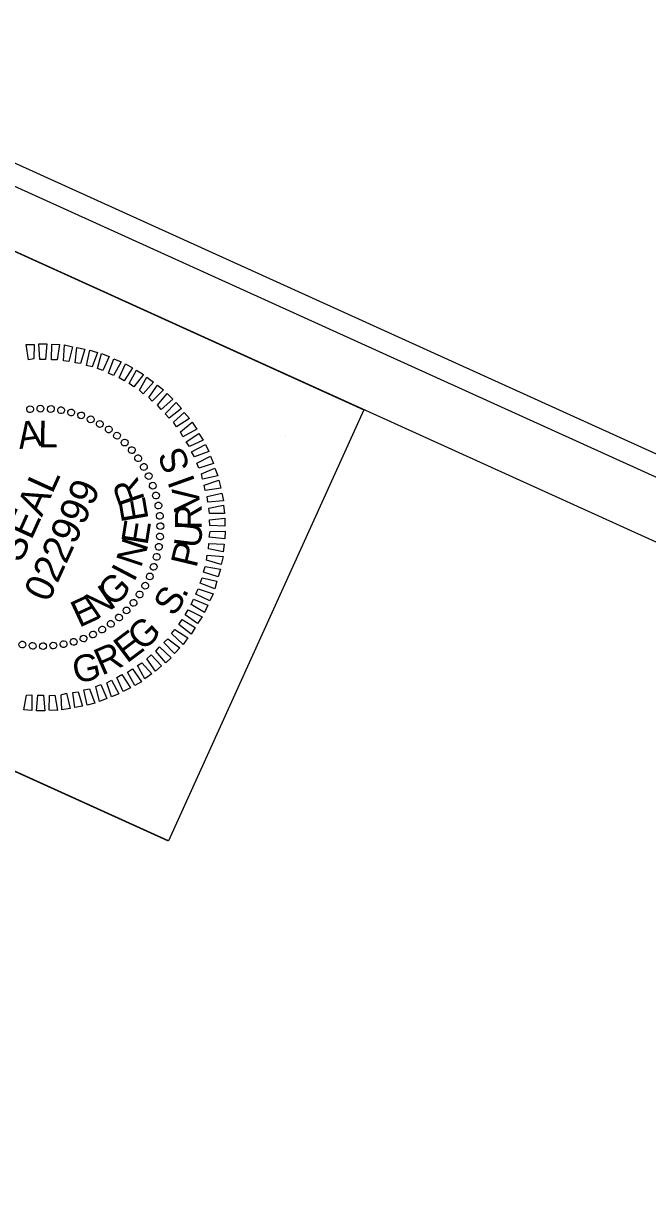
# Model space of a CAD drawing. Extents: x 1744741 to 2014229, y 466994 to 951338.
# Drawn here: x 2011187 to 2011483, y 477413 to 477976 of the extents above; entities that cross this region are included whole.
import ezdxf

# ---------------------------------------------------------------- set-up
doc = ezdxf.new("R2010")
doc.units = 0
for name, color, linetype in [('Prop Guardrail', 7, 'Continuous'), ('Sheet Plan CELL', 7, 'Continuous'), ('Sheet Plot Border Inside CELL', 7, 'Continuous'), ('Sheet Plot Border Outside CELL', 7, 'Continuous')]:
    doc.layers.add(name, color=color, linetype=linetype)

msp = doc.modelspace()

# ---------------------------------------------------------------- linework, layer by layer
at = {"layer": 'Prop Guardrail'}
for p, q in [((2011189.81, 477792.44), (2011189.81, 477792.44)), ((2011194.63, 477792.73), (2011194.63, 477792.73)), ((2011199.52, 477792.61), (2011199.52, 477792.61)), ((2011204.43, 477791.99), (2011204.43, 477791.99)), ((2011209.36, 477790.87), (2011209.36, 477790.87)), ((2011213.94, 477789.53), (2011213.94, 477789.53)), ((2011218.54, 477787.7), (2011218.54, 477787.7)), ((2011222.96, 477785.45), (2011222.96, 477785.45)), ((2011227.19, 477782.79), (2011227.19, 477782.79)), ((2011231.07, 477779.92), (2011231.07, 477779.92)), ((2011311.39, 477779.45), (2011311.39, 477779.45)), ((2011234.77, 477776.63), (2011234.77, 477776.63)), ((2011238.08, 477773.03), (2011238.08, 477773.03)), ((2011241.25, 477769.13), (2011241.25, 477769.13)), ((2011243.82, 477765), (2011243.82, 477765)), ((2011246.31, 477760.66), (2011246.31, 477760.66)), ((2011248.19, 477756.1), (2011248.19, 477756.1)), ((2011249.78, 477751.43), (2011249.78, 477751.43)), ((2011250.82, 477746.63), (2011250.82, 477746.63)), ((2011251.56, 477741.73), (2011251.56, 477741.73)), ((2011195.23, 477736.26), (2011195.23, 477736.26)), ((2011251.8, 477736.8), (2011251.8, 477736.8)), ((2011251.06, 477727.01), (2011251.06, 477727.01)), ((2011251.58, 477731.96), (2011251.58, 477731.96)), ((2011249.88, 477722.23), (2011249.88, 477722.23)), ((2011248.5, 477717.55), (2011248.5, 477717.55)), ((2011246.66, 477712.94), (2011246.66, 477712.94)), ((2011241.8, 477704.4), (2011241.8, 477704.4)), ((2011244.42, 477708.53), (2011244.42, 477708.53)), ((2011238.99, 477700.37), (2011238.99, 477700.37)), ((2011232.1, 477693.36), (2011232.1, 477693.36)), ((2011235.6, 477696.71), (2011235.6, 477696.71)), ((2011224.07, 477687.61), (2011224.07, 477687.61)), ((2011228.24, 477690.29), (2011228.24, 477690.29)), ((2011210.54, 477681.76), (2011210.54, 477681.76)), ((2011215.22, 477683.35), (2011215.22, 477683.35)), ((2011219.78, 477685.23), (2011219.78, 477685.23)), ((2011190.93, 477679.91), (2011190.93, 477679.91)), ((2011195.82, 477679.79), (2011195.82, 477679.79)), ((2011200.84, 477679.98), (2011200.84, 477679.98)), ((2011205.65, 477680.77), (2011205.65, 477680.77))]:
    msp.add_line(p, q, dxfattribs=at)
for points in [[(2011189.07, 477815.88), (2011187.94, 477823.18), (2011191.66, 477823.22), (2011191.47, 477816.27)], [(2011194.35, 477816.08), (2011193.97, 477823.41), (2011197.69, 477823.45), (2011197.07, 477816.08)], [(2011199.95, 477815.89), (2011200.07, 477823.24), (2011203.7, 477823.08), (2011202.66, 477815.89)], [(2011205.65, 477815.4), (2011206.12, 477822.97), (2011209.93, 477822.11), (2011208.23, 477815.1)], [(2011211.13, 477814.4), (2011212.01, 477821.78), (2011215.81, 477820.92), (2011213.71, 477814.1)], [(2011216.51, 477813.2), (2011218.1, 477820.51), (2011221.77, 477819.34), (2011219.2, 477812.59)], [(2011221.76, 477811.68), (2011223.75, 477818.81), (2011227.33, 477817.43), (2011224.31, 477810.77)], [(2011226.97, 477809.57), (2011229.58, 477816.41), (2011233.06, 477814.83), (2011229.43, 477808.45)], [(2011232.09, 477807.24), (2011235.11, 477813.9), (2011238.5, 477812.12), (2011234.46, 477805.92)], [(2011236.83, 477804.61), (2011240.41, 477810.88), (2011243.71, 477808.9), (2011239.05, 477802.98)], [(2011241.78, 477801.37), (2011245.32, 477807.55), (2011248.48, 477805.25), (2011243.51, 477799.72)], [(2011246.14, 477797.91), (2011250.3, 477803.81), (2011253.25, 477801.61), (2011247.87, 477796.27)], [(2011250.41, 477794.25), (2011254.93, 477799.86), (2011257.65, 477797.14), (2011252, 477792.29)], [(2011254.04, 477790.26), (2011259.17, 477795.59), (2011261.8, 477792.67), (2011255.83, 477788.21)], [(2011257.87, 477786.17), (2011262.98, 477790.9), (2011265.61, 477787.98), (2011259.36, 477784.02)], [(2011261.26, 477781.67), (2011266.78, 477786.21), (2011268.97, 477782.87), (2011262.41, 477779.3)], [(2011264.02, 477776.84), (2011270.05, 477780.9), (2011272.04, 477777.65), (2011265.51, 477774.68)], [(2011266.56, 477772.11), (2011273.12, 477775.68), (2011274.76, 477772.22), (2011267.96, 477769.74)], [(2011269.08, 477766.76), (2011275.55, 477770.13), (2011276.89, 477766.56), (2011269.98, 477764.38)], [(2011271.24, 477761.71), (2011277.63, 477764.37), (2011278.98, 477760.8), (2011271.79, 477759.11)], [(2011272.5, 477756.32), (2011279.46, 477758.6), (2011280.46, 477754.81), (2011273.05, 477753.72)], [(2011274.01, 477750.94), (2011280.9, 477752.51), (2011281.74, 477748.92), (2011274.22, 477748.13)], [(2011274.68, 477745.33), (2011281.77, 477746.81), (2011282.18, 477742.79), (2011275.03, 477742.82)], [(2011275.14, 477739.81), (2011282.41, 477740.59), (2011282.41, 477736.76), (2011275.15, 477737.09)], [(2011275.35, 477734.28), (2011282.55, 477734.35), (2011282.43, 477730.82), (2011274.85, 477731.54)], [(2011274.76, 477728.62), (2011282.03, 477728.29), (2011281.61, 477724.65), (2011274.61, 477726.09)], [(2011273.97, 477723.05), (2011281.55, 477722.33), (2011280.59, 477718.57), (2011273.61, 477720.62)], [(2011272.97, 477717.57), (2011280.32, 477716.34), (2011279.19, 477712.77), (2011272.27, 477714.93)], [(2011271.56, 477712.28), (2011278.47, 477710.63), (2011277.55, 477706.97), (2011270.65, 477709.73)], [(2011269.65, 477706.97), (2011276.74, 477704.62), (2011275.2, 477701.24), (2011268.53, 477704.51)], [(2011267.42, 477702.05), (2011274.27, 477699.19), (2011272.74, 477695.81), (2011266.3, 477699.59)], [(2011264.89, 477697.02), (2011271.52, 477693.65), (2011269.37, 477690.55), (2011263.57, 477694.66)], [(2011258.65, 477687.62), (2011264.79, 477683.73), (2011262.6, 477680.52), (2011257.06, 477685.75)], [(2011262.05, 477692.38), (2011268.23, 477688.59), (2011266.29, 477685.4), (2011260.52, 477690.11)], [(2011255.2, 477683.26), (2011260.9, 477678.95), (2011258.43, 477676.24), (2011253.4, 477681.48)], [(2011251.26, 477679.49), (2011256.8, 477674.26), (2011254.22, 477671.85), (2011249.53, 477677.31)], [(2011242.89, 477671.92), (2011247.63, 477666.56), (2011244.34, 477664.22), (2011240.78, 477670.53)], [(2011247.28, 477675.61), (2011252.31, 477670.36), (2011249.44, 477667.84), (2011245.23, 477673.82)], [(2011233.39, 477666.22), (2011237.46, 477659.93), (2011233.95, 477658.18), (2011231.07, 477664.92)], [(2011238.37, 477669.03), (2011242.73, 477662.85), (2011239.48, 477661.11), (2011236.12, 477667.33)], [(2011217.99, 477659.49), (2011220.61, 477652.74), (2011216.93, 477651.69), (2011215.29, 477658.98)], [(2011223.35, 477661.51), (2011226.27, 477654.87), (2011222.7, 477653.53), (2011220.97, 477660.61)], [(2011228.5, 477663.62), (2011231.98, 477657.1), (2011228.4, 477655.76), (2011226.19, 477662.32)], [(2011190.51, 477656.63), (2011190.59, 477649.18), (2011186.75, 477649.44), (2011187.99, 477656.53)], [(2011196.1, 477656.44), (2011196.69, 477649.01), (2011192.76, 477649.06), (2011193.38, 477656.44)], [(2011201.59, 477656.55), (2011202.72, 477649.24), (2011198.79, 477649.29), (2011198.98, 477656.25)], [(2011207.14, 477657.36), (2011208.78, 477650.08), (2011204.82, 477649.52), (2011204.6, 477656.66)], [(2011212.65, 477658.08), (2011214.73, 477651.21), (2011210.98, 477650.56), (2011210.05, 477657.78)]]:
    msp.add_lwpolyline(points, close=True, dxfattribs=at)
for centre, major_axis in [((2011189.75, 477792.36), (-0.16, 1.61)), ((2011194.67, 477792.63), (-0.02, 1.62)), ((2011199.59, 477792.47), (0.12, 1.62)), ((2011204.47, 477791.88), (0.26, 1.6)), ((2011209.29, 477790.86), (0.4, 1.57)), ((2011214, 477789.43), (0.54, 1.53)), ((2011218.57, 477787.6), (0.67, 1.48)), ((2011222.96, 477785.37), (0.79, 1.41)), ((2011227.14, 477782.77), (0.91, 1.34)), ((2011231.08, 477779.82), (1.03, 1.25)), ((2011234.74, 477776.53), (1.13, 1.16)), ((2011238.11, 477772.94), (1.23, 1.05)), ((2011241.15, 477769.06), (1.32, 0.94)), ((2011243.84, 477764.94), (1.39, 0.83)), ((2011246.16, 477760.6), (1.46, 0.7)), ((2011248.09, 477756.07), (1.52, 0.57)), ((2011249.62, 477751.39), (1.56, 0.44)), ((2011250.74, 477746.6), (1.59, 0.3)), ((2011251.43, 477741.72), (1.61, 0.16)), ((2011251.7, 477736.81), (1.62, 0.02)), ((2011251.54, 477731.89), (1.62, -0.12)), ((2011250.95, 477727), (1.6, -0.26)), ((2011249.94, 477722.18), (1.57, -0.4)), ((2011248.51, 477717.47), (1.53, -0.54)), ((2011244.45, 477708.51), (1.41, -0.79)), ((2011246.67, 477712.91), (1.48, -0.67)), ((2011241.84, 477704.33), (1.34, -0.91)), ((2011235.6, 477696.73), (1.16, -1.13)), ((2011238.89, 477700.4), (1.25, -1.03)), ((2011232.01, 477693.37), (1.05, -1.23)), ((2011219.67, 477685.32), (0.7, -1.46)), ((2011224.01, 477687.64), (0.83, -1.39)), ((2011228.14, 477690.33), (0.94, -1.32)), ((2011186.07, 477680.53), (-0.26, -1.6)), ((2011190.96, 477679.94), (-0.12, -1.62)), ((2011195.88, 477679.77), (0.02, -1.62)), ((2011200.8, 477680.04), (0.16, -1.61)), ((2011205.67, 477680.74), (0.3, -1.59)), ((2011210.47, 477681.85), (0.44, -1.56)), ((2011215.14, 477683.39), (0.57, -1.52))]:
    msp.add_ellipse(centre, major_axis=major_axis, ratio=0.999708, dxfattribs=at)
at = {"layer": 'Sheet Plan CELL'}
msp.add_line((2011024.95, 477691.7), (2011255.4, 477587.24), dxfattribs=at)
for points in [[(2011066.5, 477919.9), (2009673.19, 474845.92), (2011824.97, 473870.61), (2013218.28, 476944.58)], [(2011024.95, 477691.7), (2011117.84, 477896.63), (2011348.39, 477792.13), (2011255.5, 477587.2)]]:
    msp.add_lwpolyline(points, close=True, dxfattribs=at)
at = {"layer": 'Sheet Plot Border Inside CELL'}
msp.add_lwpolyline([(2011687.52, 473553.71), (2013235.02, 476967.87), (2011072.99, 477947.84), (2009525.49, 474533.68)], close=True, dxfattribs=at)
at = {"layer": 'Sheet Plot Border Outside CELL'}
msp.add_lwpolyline([(2011716.43, 473508.5), (2013280.18, 476958.52), (2011036.18, 477975.63), (2009472.43, 474525.61)], close=True, dxfattribs=at)

# ---------------------------------------------------------------- texts
at = {"layer": 'Prop Guardrail'}
for s, height, rotation, p in [('A', 12.69, 8.3774, (2011184.65, 477773.41)), ('L', 12.69, 359.018, (2011193.47, 477774.36)), ('S', 12.69, 109.6866, (2011265.99, 477764.64)), ('SEAL', 13.496, 65.6171, (2011185.37, 477718.86)), ('R', 12.69, 109.0985, (2011244.46, 477749.51)), ('I', 12.69, 109.6866, (2011268.37, 477757.89)), ('022999', 13.5, 65.6171, (2011198.61, 477700.12)), ('E', 12.69, 99.7412, (2011246.13, 477740.11)), ('V', 12.69, 96.4626, (2011270.92, 477744.61)), ('R', 12.69, 89.8506, (2011271.37, 477734.97)), ('E', 12.68, 81.0289, (2011245.56, 477727.4)), ('U', 12.69, 83.2387, (2011270.66, 477726.01)), ('N', 12.68, 71.6735, (2011242.4, 477716.61)), ('P', 12.69, 76.6267, (2011268.83, 477716.61)), ('I', 12.68, 62.3183, (2011239.08, 477709.84)), ('G', 12.69, 43.6074, (2011229.26, 477697.98)), ('E', 12.68, 24.894, (2011213.06, 477688.4)), ('N', 12.69, 34.2511, (2011221.17, 477692.14)), ('S', 12.69, 56.7907, (2011258.18, 477693.39)), ('.', 12.69, 63.4027, (2011263.43, 477702.25)), ('G', 12.69, 43.5667, (2011243.4, 477676.96)), ('E', 12.69, 36.9547, (2011235.76, 477671.33)), ('G', 12.69, 12.5581, (2011211.44, 477661.88)), ('R', 12.69, 23.7307, (2011223.86, 477665.69))]:
    msp.add_text(s, height=height, rotation=rotation, dxfattribs=at).set_placement(p)

doc.saveas('drawing.dxf')
